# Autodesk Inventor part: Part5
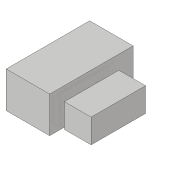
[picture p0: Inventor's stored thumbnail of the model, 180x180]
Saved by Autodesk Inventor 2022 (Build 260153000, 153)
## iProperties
Created: 2015-07
Part Number: Part5
Material: Generic
Document SubType Name: Modeling
Designer: Sandeep
Density: 1 g/cm^3
Appearance: Default
Author: Sandeep
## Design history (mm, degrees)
sketch "Sketch1"
  geometry: L1 (-7.411, 3.941)-(-1.385, 3.941); L2 (-1.385, 3.941)-(-1.385, -7.628); L3 (-1.385, -7.628)-(-7.411, -7.628); L4 (-7.411, -7.628)-(-7.411, 3.941); 1 further point
  constraints: 8 end point, 2 parallel, 1 horizontal, 1 perpendicular
extrude "Extrusion1" new body sketch "Sketch1" distance "d0" = 5; taper "d1" = 0 deg
sketch "Sketch2"
  geometry: L1 (1.52, -7.467)-(7.078, -7.467); L2 (7.078, -7.467)-(7.078, 3.854); L3 (7.078, 3.854)-(1.52, 3.854); L4 (1.52, 3.854)-(1.52, -7.467); 1 further point
  constraints: 8 end point, 2 parallel, 1 horizontal, 1 perpendicular
extrude "Extrusion2" new body sketch "Sketch2" distance "d2" = 5; taper "d3" = 0 deg
node "Direct Edit1"
body "Solid1"
body "Solid2"
feature "Scale1"
other parameters: "d4" = 15
